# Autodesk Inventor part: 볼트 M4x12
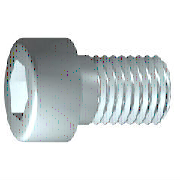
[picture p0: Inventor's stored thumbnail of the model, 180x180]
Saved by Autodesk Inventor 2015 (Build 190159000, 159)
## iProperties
IsCustomPart: 0
Created: 2015-12
Part Number: 볼트 M4x12
Material: 강철, 연강
Description: 6각머리 태핑 나사
Document SubType Name: Modeling
Standard: KS B 1003
Designer: mdu
Standards Organization: KS
Language: ko-KR
Size Designation: M 4 x 12
Categories: <MemberInstance><Categories><Category DisplayName="조임쇠" InternalName="e4da775c-781d-43d5-af7c-5136215cf5a6" Mnemonic="FSTN"><Category DisplayName="볼트" InternalN
Density: 7.86 g/cm^3
Mass: 2.23465 g
Surface Area: 3.30853 cm^2
Volume: 0.284306 cm^3
Appearance: 진녹색
Author: mdu
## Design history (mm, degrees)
sketch "스케치1"
  geometry: L1 (-1, 0)-(12, 0); L2 (12, 0)-(12, 2); L3 (12, 2)-(1.75, 2); L4 (1.75, 2)-(1.32, 2); L5 (1.32, 2)-(0, 2); L6 (0, 2)-(0, 3.5); L7 (0, 3.5)-(-4, 3.5); L8 (-4, 3.5)-(-4, 1.732); L9 (-4, 1.732)-(-2, 1.732); L10 (-2, 1.732)-(-1, 0); L11 (-7.2, 0)-(15.2, 0) reference; L12 (0, -0.7)-(0, 4.2) reference; L13 (1.75, 2)-(0, 2)
  constraints: 22 end point, 6 parallel, 2 collinear, 2 perpendicular, 1 horizontal, 1 point on line
  dimensions: "d1" = 10.25 distance from line of L3.end L2 (= GEL); "d2" = 0.42952 distance of L4.end L3.end (computed from GAL); "d3" = 4 distance between parallel lines of L8 L6 (= KOH); "d4" = 2 distance of L8.end L9.end (= INTI); "d5" = 60 deg angle of L10 L1; "d6" = 4 diameter of L3 L1 (= GD); "d7" = 4 diameter of L5 L1 (= BDM); "d8" = 3.4641 diameter of L9 L1 (= 1.1547 x SW); "d9" = 7 diameter of L7 L1 (= KOD); "d26" = 12 distance between parallel lines of L12 L2 (= NLG)
revolve "본체" sketch "스케치1" stored, may be unused: angle "d10" = 90 deg
sketch "스케치2"
  geometry: L1 (0, -4.9)-(0, 4.9) reference; L2 (-4.9, 0)-(4.9, 0) reference; L3 (1.732, 0)-(0.866, -1.5); L4 (0.866, -1.5)-(-0.866, -1.5); L5 (-0.866, -1.5)-(-1.732, 0); L6 (-1.732, 0)-(-0.866, 1.5); L7 (-0.866, 1.5)-(0.866, 1.5); L8 (0.866, 1.5)-(1.732, 0); 2 further points
  constraints: 12 end point, 1 coincident, 1 horizontal alignment, 1 point on line, 12 other
extrude "슬롯" join sketch "스케치2" stored distance "d11" = 10; taper "d12" = 0 deg
workplane "Work Plane1"
fillet "Fillet2" dims "d30" = 0.1 (= R)
body "Solid1"
fillet "모깎기1" dims "d17" = 0.4 (= RR)
feature "스레드" dims "d13" = 10.25 (= GEL), "d14" = 0
chamfer "모따기1" distance "d15" = 0.42941 (= -0.5 x SPD + 0.5 x GD); stored, may be unused: second distance "d16" = 0.42941 (= GUL), angle "d27" = 45 deg
other parameters: "GD" = 4 (= NND) [user parameter; used in 2 equation terms], "NLG" = 12 [user parameter; used in 1 equation term], "GEL" = 10.25 [user parameter; used in 2 equation terms], "KOD" = 7 [user parameter; used in 1 equation term], "KOH" = 4 [user parameter; used in 1 equation term], "INTI" = 2 [user parameter; used in 1 equation term], "GAL" = 0.42941 (= 0.61345 x PTC) [user parameter; used in 1 equation term], "GUL" = 0.42941 (= 0.61345 x PTC) [user parameter; used in 1 equation term], "BDM" = 4 (= NND) [user parameter; used in 1 equation term], "SW" = 3 [user parameter; used in 2 equation terms], "RR" = 0.4 [user parameter; used in 1 equation term], "SPD" = 3.14117 (= NND - 1.2269 x PTC) [user parameter; used in 1 equation term], "d19" = 0, "d28" = 0, "d29" = 0, "R" = 0.1 [user parameter; used in 1 equation term], "PHH" = 0.2 [user parameter], "GD1" = 3.14117 (= THREADDIA - 1.2269 x PTC) [user parameter], "THREADDIA" = 4 [user parameter; used in 1 equation term], "FAWI" = 45 deg [user parameter], "TPU" = 14.28571 (computed from PTC) [user parameter], "PTC" = 0.7 [user parameter; used in 5 equation terms], "NND" = 4 [user parameter; used in 3 equation terms], "TOA" = 30 deg [user parameter], "E0" = 3.465 (= 1.155 x SW) [user parameter]
